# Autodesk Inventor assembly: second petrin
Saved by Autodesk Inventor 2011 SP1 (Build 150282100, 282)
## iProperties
Created: 2010-12
Part Number: second petrin
Document SubType Name: Assembly
Designer: eric
Author: eric
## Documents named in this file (10)
- D:\eduinventor\maquettesaip2011\machineàpain\Workspace\second petrin.iam
- D:\eduinventor\maquettesaip2011\machineàpain\Workspace\axe de poulie du second petrin.ipt
- D:\eduinventor\maquettesaip2011\machineàpain\Workspace\accouplement d axe de poulie.ipt
- D:\eduinventor\maquettesaip2011\machineàpain\Workspace\rondelle de frottement axe de poulie.ipt
- D:\eduinventor\maquettesaip2011\machineàpain\Workspace\segment d arret.ipt
- D:\eduinventor\maquettesaip2011\machineàpain\Workspace\poulie du second petrin.ipt
- D:\eduinventor\maquettesaip2011\machineàpain\Workspace\platine de poulie.ipt
- D:\eduinventor\maquettesaip2011\machineàpain\Workspace\rondelle  M5.ipt
- D:\eduinventor\maquettesaip2011\machineàpain\Workspace\Ecrou H FR, M 5.iam
- D:\eduinventor\maquettesaip2011\machineàpain\Workspace\Rondelle, W 5.ipt
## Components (10 placed, 9 different names)
1. axe de poulie du second petrin:1
2. accouplement d axe de poulie:1
3. rondelle de frottement axe de poulie:1
4. rondelle de frottement axe de poulie:2
5. segment d arret:1
6. poulie du second petrin:1
7. platine de poulie:1
8. rondelle  M5:1
9. Ecrou H FR, M 5:1 [sub-assembly]
10. Rondelle, W 5:1
